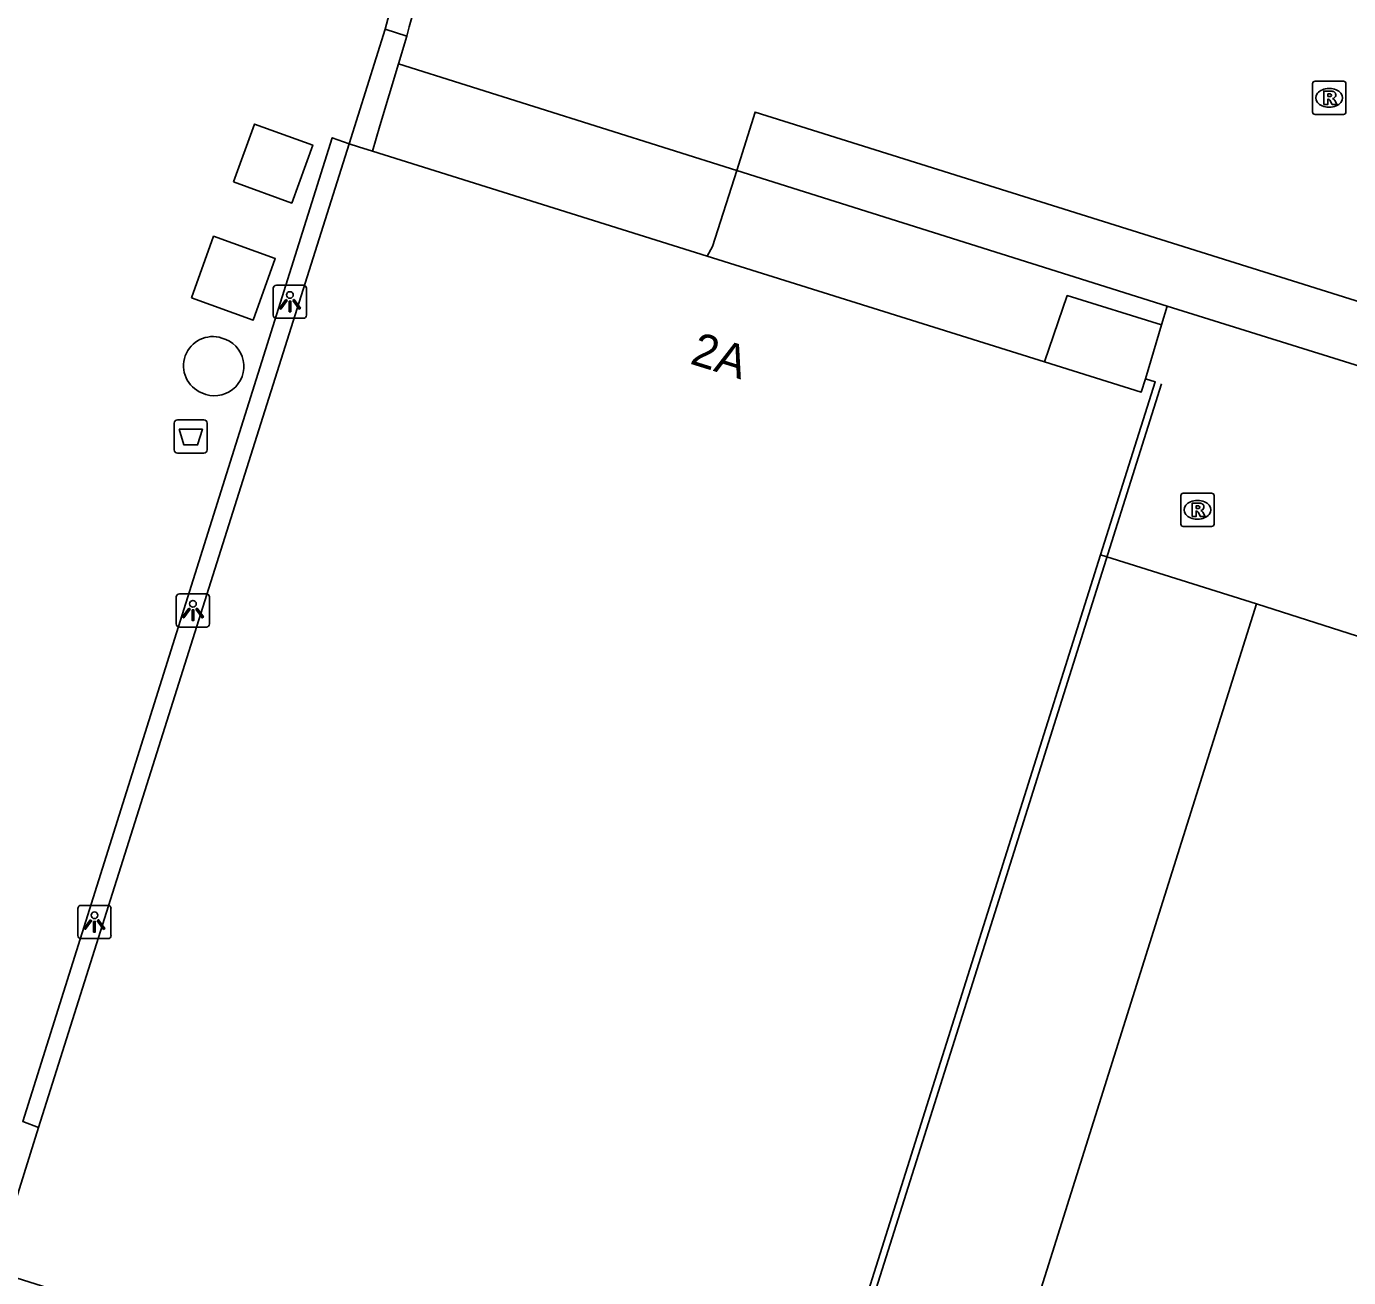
# Model space of a CAD drawing. Extents: x 160676 to 161153, y 383244 to 383713.
# Drawn here: x 161055.39 to 161095.07, y 383436.78 to 383474.33 of the extents above; entities that cross this region are included whole.
import ezdxf

# ---------------------------------------------------------------- set-up
doc = ezdxf.new("R2010")
doc.units = 0
for name, color, linetype in [('IMGEO_Afvalbak', 7, 'Continuous'), ('IMGEO_Fietspad_gesloten', 7, 'Continuous'), ('IMGEO_Grasland_overig', 7, 'Continuous'), ('IMGEO_Lichtpunt', 7, 'Continuous'), ('IMGEO_Lijnafwatering', 7, 'Continuous'), ('IMGEO_Pand', 7, 'Continuous'), ('IMGEO_Pand_nummerreeks', 7, 'Continuous'), ('IMGEO_Rijbaan_lokaal_open', 7, 'Continuous'), ('IMGEO_Rioolput', 7, 'Continuous'), ('IMGEO_Voetgangersgebied_open', 7, 'Continuous'), ('IMGEO_Voetpad_gesloten', 7, 'Continuous'), ('IMGEO_Voetpad_open', 7, 'Continuous')]:
    doc.layers.add(name, color=color, linetype=linetype)

msp = doc.modelspace()

# ---------------------------------------------------------------- linework, layer by layer
at = {"layer": 'IMGEO_Afvalbak'}
for p, q in [((161059.923, 383462.528), (161060.713, 383462.528)), ((161060.713, 383462.528), (161059.923, 383462.528)), ((161059.823, 383461.628), (161059.823, 383462.428)), ((161059.823, 383462.428), (161059.823, 383461.628)), ((161060.813, 383462.428), (161060.813, 383461.628)), ((161060.813, 383461.628), (161060.813, 383462.428)), ((161060.713, 383461.528), (161059.923, 383461.528)), ((161059.923, 383461.528), (161060.713, 383461.528))]:
    msp.add_line(p, q, dxfattribs=at)
msp.add_lwpolyline([(161059.966, 383462.242), (161060.67, 383462.242), (161060.521, 383461.772), (161060.115, 383461.772), (161059.966, 383462.242)], dxfattribs=at)
for centre, start, end in [((161059.923, 383462.428), 90, 180), ((161059.923, 383462.428), 90, 180), ((161060.713, 383462.428), 0, 90), ((161060.713, 383462.428), 360, 90), ((161059.923, 383461.628), 180, 270), ((161059.923, 383461.628), 180, 270), ((161060.713, 383461.628), 270, 0), ((161060.713, 383461.628), 270, 0)]:
    msp.add_arc(centre, 0.1, start, end, dxfattribs=at)
at = {"layer": 'IMGEO_Fietspad_gesloten'}
for points in [[(161076.702, 383470.014), (161089.617, 383465.938)], [(161089.451, 383465.38), (161086.624, 383466.255), (161085.936, 383464.272)], [(161089.617, 383465.938), (161089.451, 383465.38)], [(161089.617, 383465.938), (161116.681, 383457.491), (161117.138, 383457.349)]]:
    msp.add_lwpolyline(points, dxfattribs=at)
at = {"layer": 'IMGEO_Grasland_overig'}
msp.add_lwpolyline([(161066.152, 383474.253), (161066.803, 383474.038)], dxfattribs=at)
at = {"layer": 'IMGEO_Lichtpunt'}
for p, q in [((161062.796, 383466.476), (161062.796, 383465.669)), ((161062.796, 383466.476), (161062.796, 383465.669)), ((161063.698, 383466.571), (161062.89, 383466.571)), ((161063.698, 383466.571), (161062.89, 383466.571)), ((161063.792, 383465.669), (161063.792, 383466.476)), ((161063.792, 383465.669), (161063.792, 383466.476)), ((161062.89, 383465.575), (161063.698, 383465.575)), ((161062.89, 383465.575), (161063.698, 383465.575)), ((161059.885, 383457.21), (161059.885, 383456.403)), ((161059.885, 383457.21), (161059.885, 383456.403)), ((161060.787, 383457.305), (161059.979, 383457.305)), ((161060.787, 383457.305), (161059.979, 383457.305)), ((161060.881, 383456.403), (161060.881, 383457.21)), ((161060.881, 383456.403), (161060.881, 383457.21)), ((161059.979, 383456.309), (161060.787, 383456.309)), ((161059.979, 383456.309), (161060.787, 383456.309)), ((161056.928, 383447.859), (161056.928, 383447.052)), ((161056.928, 383447.859), (161056.928, 383447.052)), ((161057.83, 383447.954), (161057.022, 383447.954)), ((161057.83, 383447.954), (161057.022, 383447.954)), ((161057.924, 383447.052), (161057.924, 383447.859)), ((161057.924, 383447.052), (161057.924, 383447.859)), ((161057.022, 383446.958), (161057.83, 383446.958)), ((161057.022, 383446.958), (161057.83, 383446.958))]:
    msp.add_line(p, q, dxfattribs=at)
for points in [[(161063.17, 383466.14), (161063.209, 383466.112), (161063.021, 383465.85), (161062.983, 383465.877), (161063.17, 383466.14)], [(161063.272, 383466.092), (161063.319, 383466.092), (161063.319, 383465.77), (161063.272, 383465.77), (161063.272, 383466.092)], [(161063.382, 383466.112), (161063.42, 383466.139), (161063.607, 383465.877), (161063.568, 383465.849), (161063.382, 383466.112)], [(161060.259, 383456.874), (161060.298, 383456.846), (161060.11, 383456.584), (161060.072, 383456.611), (161060.259, 383456.874)], [(161060.361, 383456.826), (161060.408, 383456.826), (161060.408, 383456.504), (161060.361, 383456.504), (161060.361, 383456.826)], [(161060.471, 383456.846), (161060.509, 383456.873), (161060.696, 383456.611), (161060.657, 383456.583), (161060.471, 383456.846)], [(161057.302, 383447.523), (161057.341, 383447.495), (161057.153, 383447.233), (161057.115, 383447.26), (161057.302, 383447.523)], [(161057.404, 383447.475), (161057.451, 383447.475), (161057.451, 383447.153), (161057.404, 383447.153), (161057.404, 383447.475)], [(161057.514, 383447.495), (161057.552, 383447.522), (161057.739, 383447.26), (161057.7, 383447.232), (161057.514, 383447.495)]]:
    msp.add_lwpolyline(points, dxfattribs=at)
for centre in [(161063.295, 383466.274), (161060.384, 383457.008), (161057.427, 383447.657)]:
    msp.add_circle(centre, 0.0994, dxfattribs=at)
for centre, start, end in [((161062.89, 383466.476), 90, 180), ((161062.89, 383466.476), 90, 180), ((161063.698, 383466.476), 0, 90), ((161063.698, 383466.476), 0, 90), ((161062.89, 383465.669), 180, 270), ((161062.89, 383465.669), 180, 270), ((161063.698, 383465.669), 270, 0), ((161063.698, 383465.669), 270, 360), ((161059.979, 383457.21), 90, 180), ((161059.979, 383457.21), 90, 180), ((161060.787, 383457.21), 0, 90), ((161060.787, 383457.21), 0, 90), ((161059.979, 383456.403), 180, 270), ((161059.979, 383456.403), 180, 270), ((161060.787, 383456.403), 270, 0), ((161060.787, 383456.403), 270, 360), ((161057.022, 383447.859), 90, 180), ((161057.022, 383447.859), 90, 180), ((161057.83, 383447.859), 0, 90), ((161057.83, 383447.859), 0, 90), ((161057.022, 383447.052), 180, 270), ((161057.022, 383447.052), 180, 270), ((161057.83, 383447.052), 270, 0), ((161057.83, 383447.052), 270, 360)]:
    msp.add_arc(centre, 0.0946, start, end, dxfattribs=at)
at = {"layer": 'IMGEO_Lijnafwatering'}
for points in [[(161084.506, 383447.923), (161089.456, 383463.605)], [(161079.556, 383432.24), (161084.506, 383447.923)]]:
    msp.add_lwpolyline(points, dxfattribs=at)
at = {"layer": 'IMGEO_Pand'}
for points in [[(161065.07, 383470.806), (161055.753, 383441.293)], [(161065.769, 383470.587), (161065.355, 383470.717), (161065.07, 383470.806)], [(161075.812, 383467.442), (161065.769, 383470.587)], [(161085.936, 383464.272), (161075.812, 383467.442)], [(161088.969, 383463.756), (161088.845, 383463.361), (161085.936, 383464.272)], [(161088.969, 383463.756), (161089.265, 383463.665), (161087.625, 383458.471)], [(161087.625, 383458.471), (161079.365, 383432.3), (161079.256, 383432.332), (161079.064, 383432.389)], [(161085.837, 383436.463), (161092.303, 383457.008)], [(161092.303, 383457.008), (161099.585, 383454.678), (161099.14, 383453.302), (161113.247, 383448.803), (161107.493, 383430.819)], [(161055.753, 383441.293), (161054.395, 383436.989), (161054.702, 383436.892), (161075.255, 383430.401)]]:
    msp.add_lwpolyline(points, dxfattribs=at)
at = {"layer": 'IMGEO_Rijbaan_lokaal_open'}
for points in [[(161066.803, 383474.038), (161066.557, 383473.216)], [(161066.557, 383473.216), (161065.997, 383471.348), (161065.769, 383470.587)], [(161066.557, 383473.216), (161076.702, 383470.014)], [(161117.721, 383459.056), (161117.222, 383459.213), (161077.255, 383471.761), (161076.702, 383470.014)], [(161076.702, 383470.014), (161075.979, 383467.73), (161075.812, 383467.442)]]:
    msp.add_lwpolyline(points, dxfattribs=at)
msp.add_arc((161075.988, 383471.863), 9.439, 138.4965, 166.6785, dxfattribs=at)
at = {"layer": 'IMGEO_Rioolput'}
for p, q in [((161093.984, 383471.765), (161093.984, 383472.617)), ((161094.059, 383472.691), (161094.911, 383472.691)), ((161094.472, 383472.471), (161094.497, 383472.471)), ((161094.985, 383472.617), (161094.985, 383471.765)), ((161094.911, 383471.691), (161094.059, 383471.691)), ((161094.495, 383471.911), (161094.47, 383471.911)), ((161090.03, 383459.399), (161090.03, 383460.251)), ((161090.105, 383460.325), (161090.957, 383460.325)), ((161090.518, 383460.105), (161090.543, 383460.105)), ((161091.031, 383460.251), (161091.031, 383459.399)), ((161090.957, 383459.325), (161090.105, 383459.325)), ((161090.541, 383459.545), (161090.516, 383459.545))]:
    msp.add_line(p, q, dxfattribs=at)
for points in [[(161093.984, 383471.765), (161093.984, 383472.617)], [(161094.059, 383472.691), (161094.911, 383472.691)], [(161094.573, 383472.389), (161094.321, 383472.391), (161094.321, 383471.991)], [(161094.985, 383472.617), (161094.985, 383471.765)], [(161094.321, 383471.991), (161094.445, 383471.991), (161094.445, 383472.153), (161094.456, 383472.153)], [(161094.499, 383472.31), (161094.445, 383472.31), (161094.445, 383472.229)], [(161094.445, 383472.229), (161094.497, 383472.229)], [(161094.503, 383472.124), (161094.574, 383471.991), (161094.714, 383471.991), (161094.649, 383472.117)], [(161094.911, 383471.691), (161094.059, 383471.691)], [(161090.03, 383459.399), (161090.03, 383460.251)], [(161090.105, 383460.325), (161090.957, 383460.325)], [(161091.031, 383460.251), (161091.031, 383459.399)], [(161090.619, 383460.023), (161090.367, 383460.025), (161090.367, 383459.625)], [(161090.367, 383459.625), (161090.491, 383459.625), (161090.491, 383459.787), (161090.502, 383459.787)], [(161090.545, 383459.944), (161090.491, 383459.944), (161090.491, 383459.863)], [(161090.491, 383459.863), (161090.543, 383459.863)], [(161090.549, 383459.758), (161090.62, 383459.625), (161090.76, 383459.625), (161090.695, 383459.751)], [(161090.957, 383459.325), (161090.105, 383459.325)]]:
    msp.add_lwpolyline(points, dxfattribs=at)
for centre, radius, start, end in [((161094.061, 383472.615), 0.0765, 91.552, 178.448), ((161094.061, 383472.615), 0.0765, 91.552, 178.448), ((161094.572, 383472.279), 0.109, 350.3612, 89.416), ((161094.909, 383472.615), 0.0765, 1.552, 88.448), ((161094.909, 383472.615), 0.0765, 1.552, 88.448), ((161094.455, 383472.1), 0.0533, 26.0293, 88.6989), ((161094.481, 383472.418), 0.19, 274.7715, 282.9687), ((161094.505, 383472.214), 0.0964, 77.0061, 93.1865), ((161094.519, 383472.271), 0.0378, 276.6634, 79.6772), ((161094.57, 383472.279), 0.112, 277.5842, 350.9817), ((161094.554, 383472.064), 0.108, 29.5134, 73.7905), ((161094.061, 383471.767), 0.0765, 181.552, 268.448), ((161094.061, 383471.767), 0.0765, 181.552, 268.448), ((161094.909, 383471.767), 0.0765, 271.552, 358.448), ((161094.909, 383471.767), 0.0765, 271.552, 358.448), ((161090.107, 383460.249), 0.0765, 91.552, 178.448), ((161090.107, 383460.249), 0.0765, 91.552, 178.448), ((161090.955, 383460.249), 0.0765, 1.552, 88.448), ((161090.955, 383460.249), 0.0765, 1.552, 88.448), ((161090.501, 383459.734), 0.0533, 26.0293, 88.6989), ((161090.527, 383460.052), 0.19, 274.7715, 282.9687), ((161090.551, 383459.848), 0.0964, 77.0061, 93.1865), ((161090.565, 383459.905), 0.0378, 276.6634, 79.6772), ((161090.618, 383459.913), 0.109, 350.3612, 89.416), ((161090.616, 383459.913), 0.112, 277.5842, 350.9817), ((161090.6, 383459.698), 0.108, 29.5134, 73.7905), ((161090.107, 383459.401), 0.0765, 181.552, 268.448), ((161090.107, 383459.401), 0.0765, 181.552, 268.448), ((161090.955, 383459.401), 0.0765, 271.552, 358.448), ((161090.955, 383459.401), 0.0765, 271.552, 358.448)]:
    msp.add_arc(centre, radius, start, end, dxfattribs=at)
for centre, major_axis, ratio, start_param, end_param in [((161094.471, 383472.191), (-0.387, 0.002), 0.722429, 4.712389, 7.853982), ((161094.496, 383472.191), (-0.39, 0.002), 0.717154, 1.570796, 4.712389), ((161090.517, 383459.825), (-0.387, 0.002), 0.722429, 4.712389, 7.853982), ((161090.542, 383459.825), (-0.39, 0.002), 0.717154, 1.570796, 4.712389)]:
    msp.add_ellipse(centre, major_axis=major_axis, ratio=ratio, start_param=start_param, end_param=end_param, dxfattribs=at)
at = {"layer": 'IMGEO_Voetgangersgebied_open'}
msp.add_lwpolyline([(161087.625, 383458.471), (161092.303, 383457.008)], dxfattribs=at)
at = {"layer": 'IMGEO_Voetpad_gesloten'}
msp.add_lwpolyline([(161089.451, 383465.38), (161088.969, 383463.756)], dxfattribs=at)
at = {"layer": 'IMGEO_Voetpad_open'}
for points in [[(161065.07, 383470.806), (161066.152, 383474.253)], [(161061.601, 383469.665), (161062.229, 383471.405), (161063.978, 383470.774), (161063.35, 383469.034), (161061.601, 383469.665)], [(161055.753, 383441.293), (161055.274, 383441.468), (161064.564, 383470.995), (161065.07, 383470.806)], [(161060.342, 383466.184), (161061.005, 383468.035), (161062.855, 383467.373), (161062.192, 383465.522), (161060.342, 383466.184)]]:
    msp.add_lwpolyline(points, dxfattribs=at)
for centre, radius, start, end in [((161076.561, 383471.597), 10.743, 159.1644, 165.6856), ((161060.977, 383464.148), 0.877, 71.6819, 248.3687), ((161061.03, 383464.129), 0.881, 244.6875, 75.3631)]:
    msp.add_arc(centre, radius, start, end, dxfattribs=at)

# ---------------------------------------------------------------- texts
at = {"layer": 'IMGEO_Pand_nummerreeks'}
msp.add_text('2A', height=1, rotation=342.754, dxfattribs=at).set_placement((161075.269, 383464.221))

doc.saveas('drawing.dxf')
